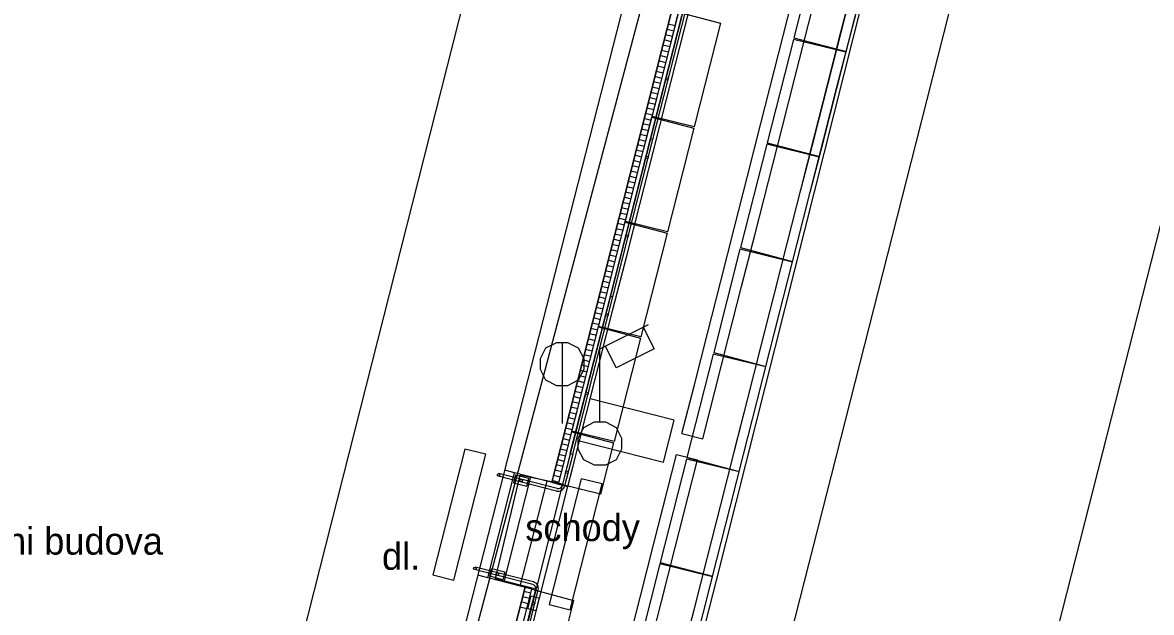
# Model space of a CAD drawing. Extents: x -733601 to -733291, y -1137892 to -1137187.
# Drawn here: x -733465.26 to -733444.38, y -1137662.74 to -1137651.84 of the extents above; entities that cross this region are included whole.
import ezdxf

# ---------------------------------------------------------------- set-up
doc = ezdxf.new("R2010")
doc.units = 0
doc.layers.add('SIT_PUV_BUS', color=7, linetype='Continuous')
doc.layers.add('SIT_PUV_ZELEZNICE', color=7, linetype='Continuous')

msp = doc.modelspace()

# ---------------------------------------------------------------- linework, layer by layer
at = {"layer": 'SIT_PUV_BUS'}
for p, q in [((-733446.02, -1137636.75), (-733452.43, -1137662.15)), ((-733451.26, -1137644.64), (-733455.27, -1137660.37)), ((-733456.56, -1137649.32), (-733464.08, -1137678.93)), ((-733453.45, -1137650.19), (-733460.1, -1137675.18)), ((-733454.58, -1137657.87), (-733453.68, -1137657.42)), ((-733453.78, -1137657.47), (-733453.58, -1137657.87)), ((-733455.68, -1137658.05), (-733455.58, -1137657.85)), ((-733455.58, -1137657.85), (-733455.38, -1137657.75)), ((-733455.38, -1137657.75), (-733455.18, -1137657.75)), ((-733455.28, -1137657.75), (-733455.28, -1137659.25)), ((-733455.18, -1137657.75), (-733454.98, -1137657.85)), ((-733454.98, -1137657.85), (-733454.88, -1137658.05)), ((-733454.28, -1137658.22), (-733454.48, -1137657.82)), ((-733455.68, -1137658.25), (-733455.68, -1137658.05)), ((-733454.88, -1137658.05), (-733454.88, -1137658.25)), ((-733454.58, -1137659.22), (-733454.58, -1137657.87)), ((-733453.58, -1137657.87), (-733454.28, -1137658.22)), ((-733455.58, -1137658.45), (-733455.68, -1137658.25)), ((-733454.88, -1137658.25), (-733454.98, -1137658.45)), ((-733455.38, -1137658.55), (-733455.58, -1137658.45)), ((-733454.98, -1137658.45), (-733455.18, -1137658.55)), ((-733455.18, -1137658.55), (-733455.38, -1137658.55)), ((-733454.98, -1137659.52), (-733454.88, -1137659.32)), ((-733454.88, -1137659.32), (-733454.68, -1137659.22)), ((-733454.68, -1137659.22), (-733454.48, -1137659.22)), ((-733454.48, -1137659.22), (-733454.28, -1137659.32)), ((-733454.28, -1137659.32), (-733454.18, -1137659.52)), ((-733454.98, -1137659.72), (-733454.98, -1137659.52)), ((-733454.18, -1137659.52), (-733454.18, -1137659.72)), ((-733454.88, -1137659.92), (-733454.98, -1137659.72)), ((-733454.18, -1137659.72), (-733454.28, -1137659.92)), ((-733454.68, -1137660.02), (-733454.88, -1137659.92)), ((-733454.28, -1137659.92), (-733454.48, -1137660.02)), ((-733454.48, -1137660.02), (-733454.68, -1137660.02)), ((-733456.06, -1137660.2), (-733456.52, -1137662.11)), ((-733455.27, -1137660.37), (-733456.06, -1137660.2)), ((-733455.27, -1137660.37), (-733460.18, -1137679.73)), ((-733452.43, -1137662.15), (-733466.53, -1137717.32)), ((-733456.52, -1137662.11), (-733455.76, -1137662.3))]:
    msp.add_line(p, q, dxfattribs=at)
at = {"layer": 'SIT_PUV_ZELEZNICE'}
for p, q in [((-733450.508, -1137650.213), (-733450.996, -1137652.122)), ((-733453.648, -1137653.988), (-733452.907, -1137651.081)), ((-733453.601, -1137654), (-733452.86, -1137651.093)), ((-733453.125, -1137651.65), (-733452.352, -1137651.855)), ((-733453.215, -1137652.001), (-733453.34, -1137651.969)), ((-733453.19, -1137651.904), (-733453.316, -1137651.872)), ((-733452.352, -1137651.855), (-733452.839, -1137653.768)), ((-733453.264, -1137652.195), (-733453.39, -1137652.163)), ((-733453.239, -1137652.098), (-733453.365, -1137652.066)), ((-733451.003, -1137652.152), (-733451.49, -1137654.061)), ((-733450.032, -1137652.389), (-733451.003, -1137652.152)), ((-733450.996, -1137652.122), (-733450.029, -1137652.379)), ((-733453.313, -1137652.389), (-733453.439, -1137652.356)), ((-733453.289, -1137652.292), (-733453.415, -1137652.259)), ((-733453.363, -1137652.583), (-733453.489, -1137652.55)), ((-733453.338, -1137652.486), (-733453.464, -1137652.453)), ((-733453.437, -1137652.873), (-733453.563, -1137652.841)), ((-733453.412, -1137652.776), (-733453.538, -1137652.744)), ((-733453.387, -1137652.679), (-733453.513, -1137652.647)), ((-733453.486, -1137653.067), (-733453.612, -1137653.035)), ((-733453.461, -1137652.97), (-733453.587, -1137652.938)), ((-733453.536, -1137653.261), (-733453.661, -1137653.228)), ((-733453.511, -1137653.164), (-733453.637, -1137653.132)), ((-733453.585, -1137653.455), (-733453.711, -1137653.422)), ((-733453.56, -1137653.358), (-733453.686, -1137653.325)), ((-733453.634, -1137653.649), (-733453.76, -1137653.616)), ((-733453.61, -1137653.552), (-733453.735, -1137653.519)), ((-733453.619, -1137653.588), (-733452.846, -1137653.793)), ((-733452.839, -1137653.768), (-733453.616, -1137653.578)), ((-733453.684, -1137653.842), (-733453.81, -1137653.81)), ((-733453.659, -1137653.745), (-733453.785, -1137653.713)), ((-733452.846, -1137653.793), (-733453.333, -1137655.706)), ((-733454.388, -1137656.896), (-733453.648, -1137653.988)), ((-733454.342, -1137656.908), (-733453.601, -1137654)), ((-733453.758, -1137654.133), (-733453.884, -1137654.101)), ((-733453.733, -1137654.036), (-733453.859, -1137654.004)), ((-733453.708, -1137653.939), (-733453.834, -1137653.907)), ((-733453.601, -1137654), (-733453.648, -1137653.988)), ((-733453.648, -1137653.988), (-733453.601, -1137654)), ((-733451.497, -1137654.09), (-733451.983, -1137655.999)), ((-733450.526, -1137654.327), (-733451.497, -1137654.09)), ((-733451.49, -1137654.061), (-733450.523, -1137654.317)), ((-733453.807, -1137654.327), (-733453.933, -1137654.294)), ((-733453.782, -1137654.23), (-733453.908, -1137654.198)), ((-733453.856, -1137654.521), (-733453.982, -1137654.488)), ((-733453.832, -1137654.424), (-733453.958, -1137654.391)), ((-733453.906, -1137654.714), (-733454.032, -1137654.682)), ((-733453.881, -1137654.618), (-733454.007, -1137654.585)), ((-733453.955, -1137654.908), (-733454.081, -1137654.876)), ((-733453.931, -1137654.811), (-733454.056, -1137654.779)), ((-733454.005, -1137655.102), (-733454.13, -1137655.07)), ((-733453.98, -1137655.005), (-733454.106, -1137654.973)), ((-733454.054, -1137655.296), (-733454.18, -1137655.263)), ((-733454.029, -1137655.199), (-733454.155, -1137655.167)), ((-733454.128, -1137655.587), (-733454.254, -1137655.554)), ((-733454.103, -1137655.49), (-733454.229, -1137655.457)), ((-733454.079, -1137655.393), (-733454.205, -1137655.36)), ((-733454.113, -1137655.526), (-733453.339, -1137655.731)), ((-733453.333, -1137655.706), (-733454.11, -1137655.516)), ((-733454.177, -1137655.78), (-733454.303, -1137655.748)), ((-733454.153, -1137655.684), (-733454.279, -1137655.651)), ((-733453.339, -1137655.731), (-733453.827, -1137657.644)), ((-733454.227, -1137655.974), (-733454.353, -1137655.942)), ((-733454.202, -1137655.877), (-733454.328, -1137655.845)), ((-733454.276, -1137656.168), (-733454.402, -1137656.136)), ((-733454.251, -1137656.071), (-733454.377, -1137656.039)), ((-733451.991, -1137656.028), (-733452.477, -1137657.937)), ((-733451.019, -1137656.265), (-733451.991, -1137656.028)), ((-733451.983, -1137655.999), (-733451.017, -1137656.255)), ((-733454.325, -1137656.362), (-733454.451, -1137656.329)), ((-733454.301, -1137656.265), (-733454.427, -1137656.233)), ((-733454.375, -1137656.556), (-733454.501, -1137656.523)), ((-733454.35, -1137656.459), (-733454.476, -1137656.426)), ((-733454.449, -1137656.846), (-733454.575, -1137656.814)), ((-733454.424, -1137656.749), (-733454.55, -1137656.717)), ((-733454.4, -1137656.653), (-733454.525, -1137656.62)), ((-733455.129, -1137659.803), (-733454.388, -1137656.896)), ((-733455.082, -1137659.815), (-733454.342, -1137656.908)), ((-733454.498, -1137657.04), (-733454.624, -1137657.008)), ((-733454.474, -1137656.943), (-733454.599, -1137656.911)), ((-733454.342, -1137656.908), (-733454.388, -1137656.896)), ((-733454.388, -1137656.896), (-733454.342, -1137656.908)), ((-733454.548, -1137657.234), (-733454.674, -1137657.202)), ((-733454.523, -1137657.137), (-733454.649, -1137657.105)), ((-733454.597, -1137657.428), (-733454.723, -1137657.395)), ((-733454.572, -1137657.331), (-733454.698, -1137657.298)), ((-733454.646, -1137657.622), (-733454.772, -1137657.589)), ((-733454.622, -1137657.525), (-733454.748, -1137657.492)), ((-733454.606, -1137657.464), (-733453.833, -1137657.669)), ((-733453.827, -1137657.644), (-733454.604, -1137657.454)), ((-733454.696, -1137657.815), (-733454.822, -1137657.783)), ((-733454.671, -1137657.719), (-733454.797, -1137657.686)), ((-733453.833, -1137657.669), (-733454.32, -1137659.582)), ((-733454.745, -1137658.009), (-733454.871, -1137657.977)), ((-733454.72, -1137657.912), (-733454.846, -1137657.88)), ((-733452.485, -1137657.966), (-733452.971, -1137659.875)), ((-733451.513, -1137658.203), (-733452.485, -1137657.966)), ((-733452.477, -1137657.937), (-733451.511, -1137658.194)), ((-733454.819, -1137658.3), (-733454.945, -1137658.268)), ((-733454.795, -1137658.203), (-733454.92, -1137658.171)), ((-733454.77, -1137658.106), (-733454.896, -1137658.074)), ((-733454.869, -1137658.494), (-733454.994, -1137658.461)), ((-733454.844, -1137658.397), (-733454.97, -1137658.364)), ((-733454.918, -1137658.688), (-733455.044, -1137658.655)), ((-733454.893, -1137658.591), (-733455.019, -1137658.558)), ((-733454.967, -1137658.881), (-733455.093, -1137658.849)), ((-733454.943, -1137658.784), (-733455.069, -1137658.752)), ((-733453.209, -1137659.188), (-733454.759, -1137658.793)), ((-733455.017, -1137659.075), (-733455.143, -1137659.043)), ((-733454.992, -1137658.978), (-733455.118, -1137658.946)), ((-733455.066, -1137659.269), (-733455.192, -1137659.237)), ((-733455.041, -1137659.172), (-733455.167, -1137659.14)), ((-733453.406, -1137659.963), (-733453.209, -1137659.188)), ((-733455.14, -1137659.56), (-733455.266, -1137659.527)), ((-733455.115, -1137659.463), (-733455.241, -1137659.43)), ((-733455.091, -1137659.366), (-733455.217, -1137659.334)), ((-733455.1, -1137659.402), (-733454.327, -1137659.607)), ((-733454.32, -1137659.582), (-733455.097, -1137659.392)), ((-733453.064, -1137659.431), (-733452.676, -1137659.53)), ((-733457.079, -1137659.719), (-733457.672, -1137662.044)), ((-733456.692, -1137659.817), (-733457.079, -1137659.719)), ((-733455.189, -1137659.754), (-733455.315, -1137659.721)), ((-733455.165, -1137659.657), (-733455.291, -1137659.624)), ((-733454.956, -1137659.568), (-733453.406, -1137659.963)), ((-733454.327, -1137659.607), (-733454.567, -1137660.551)), ((-733457.284, -1137662.143), (-733456.692, -1137659.817)), ((-733455.239, -1137659.947), (-733455.365, -1137659.915)), ((-733455.214, -1137659.85), (-733455.34, -1137659.818)), ((-733455.129, -1137659.803), (-733455.279, -1137660.394)), ((-733455.082, -1137659.815), (-733455.233, -1137660.406)), ((-733455.129, -1137659.803), (-733455.082, -1137659.815)), ((-733455.129, -1137659.803), (-733455.082, -1137659.815)), ((-733452.978, -1137659.904), (-733453.465, -1137661.813)), ((-733453.163, -1137659.819), (-733452.775, -1137659.917)), ((-733452.007, -1137660.141), (-733452.978, -1137659.904)), ((-733452.971, -1137659.875), (-733452.004, -1137660.132)), ((-733456.16, -1137660.159), (-733456.341, -1137660.113)), ((-733455.288, -1137660.141), (-733455.414, -1137660.109)), ((-733455.264, -1137660.044), (-733455.389, -1137660.012)), ((-733455.384, -1137660.495), (-733456.46, -1137660.221)), ((-733455.372, -1137660.449), (-733456.448, -1137660.174)), ((-733456.139, -1137660.201), (-733456.176, -1137660.346)), ((-733456.176, -1137660.346), (-733455.934, -1137660.408)), ((-733455.346, -1137660.367), (-733456.16, -1137660.159)), ((-733455.897, -1137660.262), (-733456.139, -1137660.201)), ((-733455.934, -1137660.408), (-733455.897, -1137660.262)), ((-733454.928, -1137660.267), (-733455.521, -1137662.592)), ((-733455.338, -1137660.335), (-733455.463, -1137660.303)), ((-733455.313, -1137660.238), (-733455.439, -1137660.206)), ((-733454.567, -1137660.551), (-733455.344, -1137660.361)), ((-733454.54, -1137660.365), (-733454.928, -1137660.267)), ((-733455.346, -1137660.367), (-733455.171, -1137660.411)), ((-733455.133, -1137662.691), (-733454.54, -1137660.365)), ((-733453.465, -1137661.813), (-733452.498, -1137662.07)), ((-733455.823, -1137662.22), (-733456.9, -1137661.946)), ((-733455.811, -1137662.174), (-733456.888, -1137661.899)), ((-733456.616, -1137662.071), (-733456.579, -1137661.926)), ((-733456.579, -1137661.926), (-733456.336, -1137661.987)), ((-733456.336, -1137661.987), (-733456.373, -1137662.133)), ((-733453.472, -1137661.842), (-733453.958, -1137663.751)), ((-733452.5, -1137662.079), (-733453.472, -1137661.842)), ((-733457.672, -1137662.044), (-733457.284, -1137662.143)), ((-733456.653, -1137662.097), (-733456.836, -1137662.051)), ((-733455.839, -1137662.305), (-733456.653, -1137662.097)), ((-733456.373, -1137662.133), (-733456.616, -1137662.071)), ((-733456.116, -1137663.679), (-733455.768, -1137662.313)), ((-733456.07, -1137663.691), (-733455.721, -1137662.325)), ((-733455.884, -1137662.479), (-733456.01, -1137662.447)), ((-733455.859, -1137662.382), (-733455.985, -1137662.35)), ((-733455.913, -1137662.673), (-733455.851, -1137662.431)), ((-733455.851, -1137662.431), (-733455.706, -1137662.468)), ((-733455.841, -1137662.31), (-733455.067, -1137662.515)), ((-733455.839, -1137662.305), (-733455.665, -1137662.349)), ((-733455.933, -1137662.673), (-733456.059, -1137662.641)), ((-733455.908, -1137662.576), (-733456.034, -1137662.544)), ((-733455.706, -1137662.468), (-733455.767, -1137662.71)), ((-733455.067, -1137662.515), (-733455.555, -1137664.428)), ((-733455.521, -1137662.592), (-733455.133, -1137662.691)), ((-733455.767, -1137662.71), (-733455.913, -1137662.673))]:
    msp.add_line(p, q, dxfattribs=at)
for points in [[(-733469.582, -1137755.14), (-733468.663, -1137751.534), (-733466.195, -1137741.843), (-733463.726, -1137732.153), (-733461.257, -1137722.462), (-733458.789, -1137712.772), (-733456.32, -1137703.081), (-733453.852, -1137693.391), (-733451.383, -1137683.701), (-733451.044, -1137682.371), (-733448.914, -1137674.01), (-733446.443, -1137664.32), (-733443.966, -1137654.632), (-733441.48, -1137644.946), (-733438.982, -1137635.263), (-733436.47, -1137625.584), (-733433.94, -1137615.909), (-733431.39, -1137606.239), (-733431.038, -1137604.913), (-733428.815, -1137596.577), (-733426.217, -1137586.92), (-733424.808, -1137581.736)], [(-733473.591, -1137751.638), (-733472.603, -1137747.76), (-733470.135, -1137738.069), (-733467.666, -1137728.379), (-733465.198, -1137718.688), (-733462.729, -1137708.998), (-733460.26, -1137699.307), (-733457.792, -1137689.617), (-733455.323, -1137679.926), (-733452.855, -1137670.236), (-733450.386, -1137660.545), (-733448.734, -1137654.061), (-733447.917, -1137650.855), (-733445.432, -1137641.168), (-733442.928, -1137631.487), (-733440.405, -1137621.811), (-733437.862, -1137612.139), (-733437.8, -1137611.906), (-733435.314, -1137602.469), (-733432.775, -1137592.797), (-733432.613, -1137592.177)], [(-733453.064, -1137659.431), (-733452.841, -1137658.557), (-733452.594, -1137657.587), (-733452.347, -1137656.618), (-733452.101, -1137655.648), (-733451.854, -1137654.679), (-733451.607, -1137653.709), (-733451.359, -1137652.74), (-733451.112, -1137651.77), (-733450.865, -1137650.8), (-733450.617, -1137649.83), (-733450.369, -1137648.861), (-733450.121, -1137647.891), (-733449.873, -1137646.921), (-733449.624, -1137645.952), (-733449.376, -1137644.982), (-733449.127, -1137644.012), (-733448.878, -1137643.043), (-733448.628, -1137642.073), (-733448.379, -1137641.104), (-733448.129, -1137640.135), (-733447.978, -1137639.548)], [(-733452.676, -1137659.53), (-733452.454, -1137658.656), (-733452.207, -1137657.686), (-733451.96, -1137656.717), (-733451.713, -1137655.747), (-733451.466, -1137654.778), (-733451.219, -1137653.808), (-733450.972, -1137652.838), (-733450.725, -1137651.869), (-733450.477, -1137650.899), (-733450.229, -1137649.929), (-733449.982, -1137648.96), (-733449.734, -1137647.99), (-733449.485, -1137647.02), (-733449.237, -1137646.051), (-733448.988, -1137645.081), (-733448.739, -1137644.112), (-733448.49, -1137643.142), (-733448.241, -1137642.173), (-733447.992, -1137641.204), (-733447.742, -1137640.234), (-733447.591, -1137639.648)], [(-733455.472, -1137660.335), (-733455.38, -1137659.975), (-733455.133, -1137659.006), (-733454.886, -1137658.036), (-733454.639, -1137657.067), (-733454.392, -1137656.097), (-733454.145, -1137655.128), (-733453.898, -1137654.158), (-733453.651, -1137653.188), (-733453.404, -1137652.218), (-733453.157, -1137651.248), (-733452.909, -1137650.278), (-733452.898, -1137650.234), (-733452.661, -1137649.308), (-733452.413, -1137648.338), (-733452.165, -1137647.368), (-733451.917, -1137646.398), (-733451.668, -1137645.428), (-733451.419, -1137644.458), (-733451.17, -1137643.488), (-733450.921, -1137642.518), (-733450.672, -1137641.548), (-733450.422, -1137640.578), (-733450.27, -1137639.988)], [(-733455.346, -1137660.367), (-733455.254, -1137660.007), (-733455.007, -1137659.038), (-733454.76, -1137658.068), (-733454.513, -1137657.099), (-733454.266, -1137656.129), (-733454.019, -1137655.16), (-733453.772, -1137654.19), (-733453.525, -1137653.22), (-733453.278, -1137652.251), (-733453.031, -1137651.28), (-733452.783, -1137650.31), (-733452.535, -1137649.34), (-733452.287, -1137648.37), (-733452.039, -1137647.4), (-733451.791, -1137646.43), (-733451.542, -1137645.46), (-733451.294, -1137644.49), (-733451.045, -1137643.52), (-733450.795, -1137642.55), (-733450.546, -1137641.58), (-733450.296, -1137640.61), (-733450.145, -1137640.02)], [(-733462.935, -1137685.963), (-733461.332, -1137679.64), (-733453.759, -1137650.014), (-733456.593, -1137649.288), (-733465.899, -1137646.951)], [(-733452.1, -1137659.778), (-733451.853, -1137658.809), (-733451.606, -1137657.839), (-733451.359, -1137656.87), (-733451.112, -1137655.9), (-733450.865, -1137654.931), (-733450.618, -1137653.961), (-733450.371, -1137652.991), (-733450.124, -1137652.022), (-733449.876, -1137651.052)], [(-733452.092, -1137659.747), (-733451.853, -1137658.809), (-733451.606, -1137657.839), (-733451.359, -1137656.87), (-733451.112, -1137655.9), (-733450.864, -1137654.931), (-733450.616, -1137653.961), (-733450.368, -1137652.992), (-733450.12, -1137652.023), (-733449.872, -1137651.053)], [(-733451.926, -1137659.823), (-733451.679, -1137658.853), (-733451.432, -1137657.884), (-733451.185, -1137656.914), (-733450.938, -1137655.945), (-733450.691, -1137654.975), (-733450.444, -1137654.006), (-733450.197, -1137653.036), (-733449.949, -1137652.066), (-733449.702, -1137651.097)], [(-733451.926, -1137659.823), (-733451.679, -1137658.853), (-733451.432, -1137657.884), (-733451.184, -1137656.914), (-733450.937, -1137655.945), (-733450.69, -1137654.975), (-733450.442, -1137654.006), (-733450.194, -1137653.037), (-733449.946, -1137652.067), (-733449.697, -1137651.098)], [(-733453.157, -1137651.248), (-733453.404, -1137652.218), (-733453.651, -1137653.188), (-733453.898, -1137654.158), (-733454.145, -1137655.128), (-733454.392, -1137656.097), (-733454.639, -1137657.067), (-733454.886, -1137658.036), (-733455.133, -1137659.006), (-733455.38, -1137659.975), (-733455.469, -1137660.323), (-733455.452, -1137660.34), (-733455.346, -1137660.367), (-733455.344, -1137660.361), (-733455.254, -1137660.007), (-733455.1, -1137659.402), (-733455.097, -1137659.392), (-733455.007, -1137659.038), (-733454.76, -1137658.068), (-733454.606, -1137657.464), (-733454.604, -1137657.454), (-733454.513, -1137657.099), (-733454.266, -1137656.129), (-733454.113, -1137655.526), (-733454.11, -1137655.516), (-733454.019, -1137655.16), (-733453.772, -1137654.19), (-733453.619, -1137653.588), (-733453.616, -1137653.578), (-733453.525, -1137653.22), (-733453.278, -1137652.251), (-733453.125, -1137651.65)], [(-733455.171, -1137660.411), (-733455.08, -1137660.052), (-733454.833, -1137659.082), (-733454.586, -1137658.113), (-733454.339, -1137657.143), (-733454.092, -1137656.174), (-733453.845, -1137655.204), (-733453.598, -1137654.235), (-733453.351, -1137653.265), (-733453.104, -1137652.295), (-733452.856, -1137651.325)], [(-733454.076, -1137663.404), (-733453.829, -1137662.435), (-733453.582, -1137661.465), (-733453.335, -1137660.496), (-733453.163, -1137659.819)], [(-733453.689, -1137663.503), (-733453.442, -1137662.534), (-733453.195, -1137661.564), (-733452.948, -1137660.595), (-733452.775, -1137659.917)], [(-733453.088, -1137663.656), (-733452.841, -1137662.687), (-733452.594, -1137661.717), (-733452.347, -1137660.748), (-733452.1, -1137659.778)], [(-733452.913, -1137663.7), (-733452.666, -1137662.731), (-733452.419, -1137661.762), (-733452.172, -1137660.792), (-733451.926, -1137659.823)], [(-733456.653, -1137662.097), (-733456.16, -1137660.159)], [(-733456.353, -1137662.174), (-733455.859, -1137660.236)], [(-733456.053, -1137662.251), (-733455.559, -1137660.312)], [(-733455.827, -1137662.983), (-733455.58, -1137662.014), (-733455.333, -1137661.045), (-733455.171, -1137660.411)], [(-733456.615, -1137664.822), (-733455.965, -1137662.273)], [(-733456.489, -1137664.854), (-733455.839, -1137662.305)]]:
    msp.add_lwpolyline(points, dxfattribs=at)
msp.add_lwpolyline([(-733455.839, -1137662.305), (-733455.965, -1137662.273), (-733456.615, -1137664.822), (-733456.862, -1137665.791), (-733457.109, -1137666.761), (-733457.323, -1137667.603), (-733457.197, -1137667.635), (-733456.983, -1137666.793), (-733456.828, -1137666.186), (-733456.826, -1137666.176), (-733456.736, -1137665.824), (-733456.489, -1137664.854), (-733456.334, -1137664.248), (-733456.332, -1137664.238), (-733455.841, -1137662.31)], close=True, dxfattribs=at)
for centre in [(-733453.34, -1137652.88), (-733453.711, -1137654.334), (-733454.081, -1137655.787), (-733454.451, -1137657.241), (-733454.822, -1137658.694), (-733455.192, -1137660.148), (-733456.454, -1137660.198), (-733456.037, -1137660.304), (-733456.894, -1137661.923), (-733456.476, -1137662.029), (-733455.809, -1137662.571)]:
    msp.add_circle(centre, 0.0241, dxfattribs=at)
for centre, radius, start, end in [((-733455.353, -1137660.375), 0.124, 255.7084, 345.7084), ((-733455.353, -1137660.375), 0.0758, 255.7084, 345.7084), ((-733455.842, -1137662.294), 0.0759, 345.7084, 75.7084), ((-733455.842, -1137662.294), 0.124, 345.7084, 75.7084)]:
    msp.add_arc(centre, radius, start, end, dxfattribs=at)

# ---------------------------------------------------------------- texts
at = {"layer": 'SIT_PUV_BUS'}
for s, p in [('schody', (-733455.96, -1137661.42)), ('vypravni budova', (-733467.53, -1137661.67)), ('dl.', (-733458.61, -1137661.95))]:
    msp.add_text(s, height=0.5, dxfattribs=at).set_placement(p)

doc.saveas('drawing.dxf')
